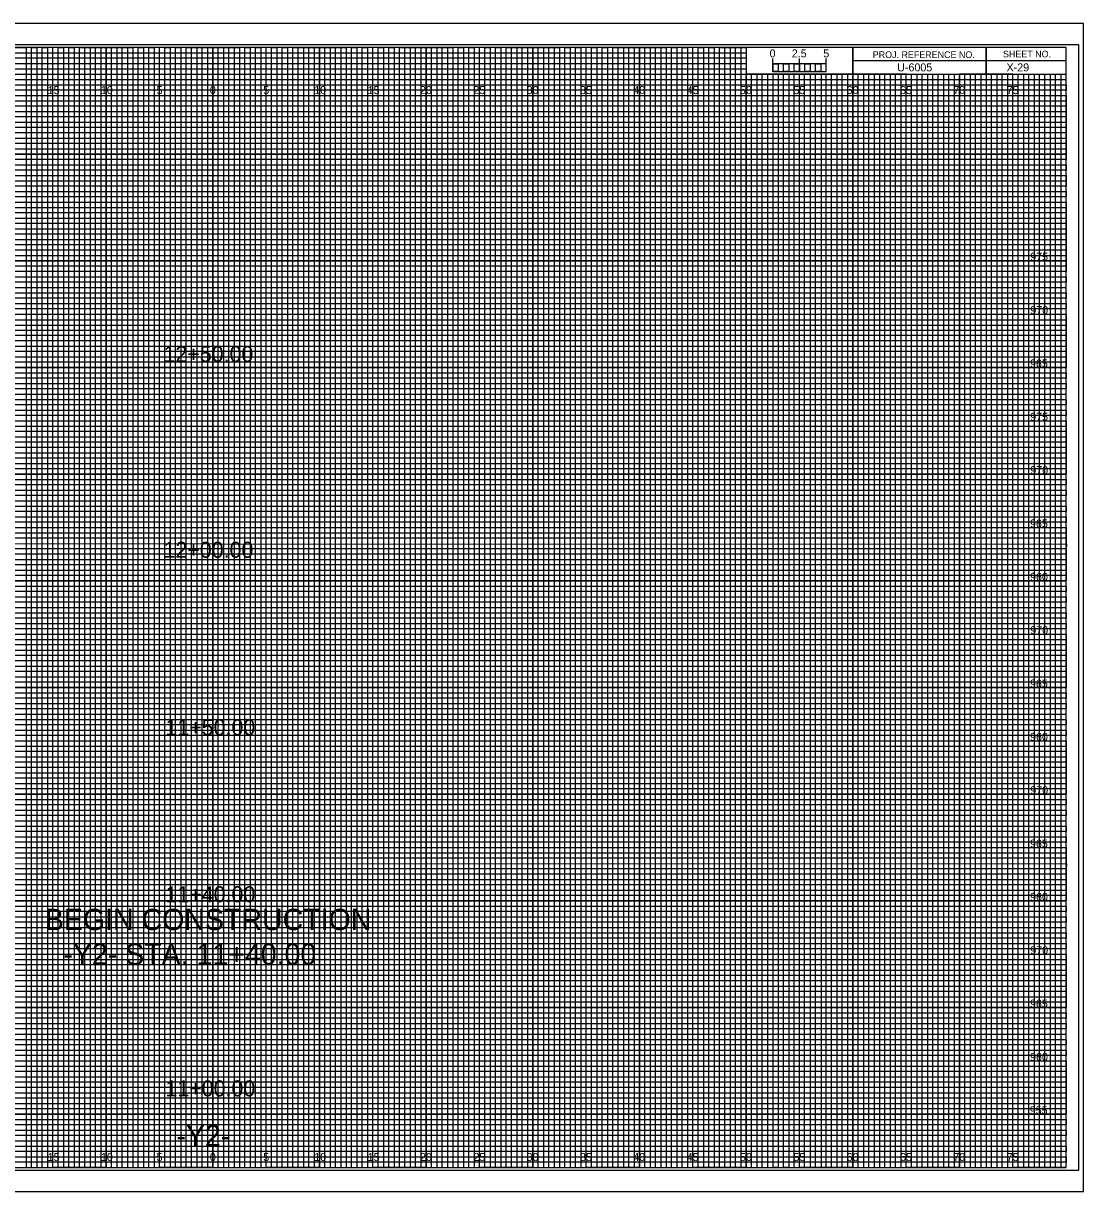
# Model space of a CAD drawing. Extents: x -7 to 162, y -2 to 107.
# Drawn here: x 62.2 to 161.7, y -2.3 to 107.3 of the extents above; entities that cross this region are included whole.
import ezdxf

# ---------------------------------------------------------------- set-up
doc = ezdxf.new("R2010")
doc.units = 0
for name, color, linetype in [('Prop XS Alignment Label', 7, 'Continuous'), ('Prop XS Bar Scale Labels', 7, 'Continuous'), ('Prop XS Elevation Labels', 7, 'Continuous'), ('Prop XS Label Text', 7, 'Continuous'), ('Prop XS Offset Labels', 7, 'Continuous'), ('Prop XS Project Number', 7, 'Continuous'), ('Prop XS Sheet Number', 7, 'Continuous'), ('Prop XS Station Labels', 7, 'Continuous'), ('Sheet Cross Section CELL', 7, 'Continuous'), ('Sheet Cross Section Grid Major CELL', 7, 'Continuous'), ('Sheet Cross Section Grid Middle CELL', 7, 'Continuous'), ('Sheet Cross Section Grid Minor 1 CELL', 7, 'Continuous'), ('Sheet Cross Section Grid Minor 2 CELL', 7, 'Continuous'), ('Sheet Cross Section Scale CELL', 7, 'Continuous'), ('Sheet Cutting Line CELL', 7, 'Continuous'), ('Sheet DOT Grid CELL', 7, 'Continuous'), ('Sheet Plot Border Inside CELL', 7, 'Continuous'), ('Sheet Plot Border Outside CELL', 7, 'Continuous')]:
    doc.layers.add(name, color=color, linetype=linetype)

msp = doc.modelspace()

# ---------------------------------------------------------------- linework, layer by layer
at = {"layer": 'Sheet Cross Section CELL'}
for p, q in [((152.5, 105), (152.5, 102.5)), ((152.5, 102.5), (152.5, 105)), ((160, 103.75), (140, 103.75)), ((140, 103.75), (140, 102.5)), ((140, 102.5), (160, 102.5))]:
    msp.add_line(p, q, dxfattribs=at)
for points in [[(160, 105), (0, 105), (0, 0), (160, 0)], [(140, 105), (130, 105), (130, 102.52), (140, 102.52)], [(160, 105), (140, 105), (140, 102.5), (160, 102.5)]]:
    msp.add_lwpolyline(points, close=True, dxfattribs=at)
at = {"layer": 'Sheet Cross Section Grid Major CELL'}
for p, q in [((65, 105), (60, 105)), ((65, 0), (65, 105)), ((75, 105), (70, 105)), ((70, 105), (70, 0)), ((75, 0), (75, 105)), ((85, 105), (80, 105)), ((80, 105), (80, 0)), ((85, 0), (85, 105)), ((95, 105), (90, 105)), ((90, 105), (90, 0)), ((95, 0), (95, 105)), ((105, 105), (100, 105)), ((100, 105), (100, 0)), ((105, 0), (105, 105)), ((115, 105), (110, 105)), ((110, 105), (110, 0)), ((115, 0), (115, 105)), ((125, 105), (120, 105)), ((120, 105), (120, 0)), ((125, 0), (125, 105)), ((130, 105), (130, 0)), ((135, 0), (135, 102.5)), ((145, 102.5), (140, 102.5)), ((140, 102.5), (140, 0)), ((145, 0), (145, 102.5)), ((155, 102.5), (150, 102.5)), ((150, 102.5), (150, 0)), ((155, 0), (155, 102.5)), ((70, 0), (65, 0)), ((80, 0), (75, 0)), ((90, 0), (85, 0)), ((100, 0), (95, 0)), ((110, 0), (105, 0)), ((120, 0), (115, 0)), ((130, 0), (125, 0)), ((140, 0), (135, 0)), ((150, 0), (145, 0)), ((160, 0), (155, 0)), ((160, 0), (160, 0))]:
    msp.add_line(p, q, dxfattribs=at)
for points in [[(0, 100), (160, 100), (160, 95), (0, 95)], [(0, 90), (160, 90), (160, 85), (0, 85)], [(0, 80), (160, 80), (160, 75), (0, 75)], [(0, 70), (160, 70), (160, 65), (0, 65)], [(0, 60), (160, 60), (160, 55), (0, 55)], [(0, 50), (160, 50), (160, 45), (0, 45)], [(0, 40), (160, 40), (160, 35), (0, 35)], [(0, 30), (160, 30), (160, 25), (0, 25)], [(0, 20), (160, 20), (160, 15), (0, 15)], [(0, 10), (160, 10), (160, 5), (0, 5)]]:
    msp.add_lwpolyline(points, dxfattribs=at)
at = {"layer": 'Sheet Cross Section Grid Middle CELL'}
for points in [[(57.5, 105), (62.5, 105), (62.5, 0), (67.5, 0), (67.5, 105), (72.5, 105), (72.5, 0), (77.5, 0), (77.5, 105), (82.5, 105), (82.5, 0), (87.5, 0), (87.5, 105), (92.5, 105), (92.5, 0), (97.5, 0), (97.5, 105), (102.5, 105), (102.5, 0), (107.5, 0), (107.5, 105), (112.5, 105), (112.5, 0), (117.5, 0), (117.5, 105), (122.5, 105), (122.5, 0), (127.5, 0), (127.5, 105), (129.97, 105), (130, 105), (130, 102.5), (132.5, 102.5), (132.5, 0), (137.5, 0), (137.5, 102.5), (142.5, 102.5), (142.5, 0), (147.5, 0), (147.5, 102.5), (152.5, 102.5), (152.5, 0), (157.5, 0), (157.5, 102.5)], [(0, 102.5), (137.5, 102.5)], [(0, 92.5), (160, 92.5), (160, 97.5), (0, 97.5)], [(0, 82.5), (160, 82.5), (160, 87.5), (0, 87.5)], [(0, 72.5), (160, 72.5), (160, 77.5), (0, 77.5)], [(0, 62.5), (160, 62.5), (160, 67.5), (0, 67.5)], [(0, 52.5), (160, 52.5), (160, 57.5), (0, 57.5)], [(0, 42.5), (160, 42.5), (160, 47.5), (0, 47.5)], [(0, 32.5), (160, 32.5), (160, 37.5), (0, 37.5)], [(0, 22.5), (160, 22.5), (160, 27.5), (0, 27.5)], [(0, 12.5), (160, 12.5), (160, 17.5), (0, 17.5)], [(0, 2.5), (160, 2.5), (160, 7.5), (0, 7.5)]]:
    msp.add_lwpolyline(points, dxfattribs=at)
at = {"layer": 'Sheet Cross Section Grid Minor 1 CELL'}
for p, q in [((0, 104.5), (130, 104.5)), ((130, 104.5), (130, 103.99)), ((130, 103.99), (0, 103.99)), ((0, 103.5), (130, 103.5)), ((130, 102.95), (0, 102.95)), ((130, 103.5), (130, 102.95)), ((0, 102), (160, 102))]:
    msp.add_line(p, q, dxfattribs=at)
for points in [[(0, 101.5), (135, 101.5), (160, 101.5), (160, 101), (0, 101)], [(0, 100.5), (160, 100.5), (160, 99.5), (0, 99.5)], [(0, 99), (160, 99), (160, 98.5), (0, 98.49)], [(0, 98), (160, 98), (160, 97), (0, 97)], [(0, 96.5), (160, 96.5), (160, 96), (0, 96)], [(0, 95.5), (160, 95.5), (160, 94.5), (0, 94.5)], [(0, 94), (160, 94), (160, 93.5), (0, 93.5)], [(0, 93), (160, 93), (160, 92), (0, 92)], [(0, 91.5), (160, 91.5), (160, 91), (0, 91)], [(0, 90.5), (160, 90.5), (160, 89.5), (0, 89.5)], [(0, 89), (160, 89), (160, 88.5), (0, 88.5)], [(0, 88), (160, 88), (160, 86.98), (160, 86.5), (160, 86), (0, 86)], [(0, 87), (160, 87), (160, 86.5), (0, 86.5)], [(0, 85.5), (160, 85.5), (160, 84.5), (0, 84.52)], [(0, 84.52), (160, 84.5), (160, 84), (0, 84)], [(0, 83.5), (160, 83.5), (160, 83), (0, 83)], [(0, 82), (160, 82), (160, 81.5), (0, 81.5)], [(0, 81), (160, 81), (160, 80.5), (0, 80.5)], [(-0.04, 79.45), (160, 79.45), (160, 78.94), (-0.04, 78.94)], [(0, 78.5), (160, 78.5), (160, 78), (0, 78)], [(0, 77), (160, 77), (160, 76.5), (0, 76.5)], [(0, 76), (160, 76), (160, 75.5), (0, 75.5)], [(0, 74.5), (160, 74.5), (160, 74), (0, 74)], [(0, 73.5), (160, 73.5), (160, 73), (0, 73)], [(0, 72), (160, 72), (160, 71.5), (0, 71.5)], [(0, 71), (160, 71), (160, 70.5), (0, 70.5)], [(0, 69.5), (160, 69.5), (160, 68.99), (0, 69)], [(0, 68.5), (160, 68.5), (160, 68), (0, 68)], [(0, 67), (160, 67), (160, 66.5), (0, 66.5)], [(0, 66), (160, 66), (160, 65.5), (0, 65.5)], [(0, 64.5), (160, 64.5), (160, 64), (0, 64)], [(0, 63.5), (160, 63.5), (160, 63), (0, 63)], [(0, 62), (160, 62), (160, 61.5), (0, 61.5)], [(0, 61), (160, 61), (160, 60.5), (0, 60.5)], [(0, 59.5), (160, 59.5), (160, 59), (0, 59)], [(0, 58.5), (160.03, 58.45), (160, 58), (0, 58)], [(0, 57), (160, 57), (160, 56.5), (0, 56.5)], [(0, 56), (160, 56), (160, 55.5), (0, 55.5)], [(0, 54.5), (160, 54.5), (160, 54), (0, 54)], [(0, 53.5), (160, 53.5), (160, 53), (0, 53)], [(0, 52), (160, 52), (160, 51.5), (0, 51.5)], [(0, 51), (160, 51), (160, 50.5), (0, 50.5)], [(0, 49.5), (160, 49.5), (160, 49), (0, 49)], [(0, 48.5), (160, 48.5), (160, 48), (0, 48)], [(0, 47), (160, 47), (160, 46.5), (0, 46.5)], [(0, 46), (160, 46), (160, 45.5), (0, 45.5)], [(0, 44.5), (160, 44.5), (160, 44), (0, 44)], [(0, 43.5), (160, 43.5), (160, 43), (0, 43)], [(0, 42), (160, 42), (160, 41.5), (0, 41.5)], [(0, 41), (160, 41), (160, 40.5), (0, 40.5)], [(0, 39.5), (160, 39.5), (160, 38.99), (0, 39)], [(0, 38.5), (160, 38.5), (160, 38), (0, 38)], [(0, 37), (160, 37), (160, 36.5), (0, 36.5)], [(0, 36), (160, 36), (160, 35.5), (0, 35.5)], [(0, 34.5), (160, 34.5), (160, 34), (0, 34)], [(0, 33.5), (160, 33.5), (160, 33), (0, 33)], [(0, 32), (160, 32), (160, 31.5), (0, 31.5)], [(0, 31), (160, 31), (160, 30.5), (0, 30.5)], [(0, 29.5), (160, 29.5), (160, 29), (0, 29)], [(0, 28.5), (160.03, 28.46), (160, 28), (0, 28)], [(0, 27), (160, 27), (160, 26.5), (0, 26.5)], [(0, 26), (160, 26), (160, 25.5), (0, 25.5)], [(0, 24.5), (160, 24.5), (160, 24), (0, 24)], [(0, 23.5), (160, 23.5), (160, 23), (0, 23)], [(0, 22), (160, 22), (160, 21.5), (0, 21.5)], [(0, 21), (160, 21), (160, 20.5), (0, 20.5)], [(0, 19.5), (160, 19.5), (160, 19), (0, 19)], [(0, 18.5), (160, 18.5), (160, 18), (0, 18)], [(0, 17), (160, 17), (160, 16.5), (0, 16.5)], [(0, 16), (160, 16), (160, 15.5), (0, 15.5)], [(0, 14.5), (160, 14.5), (160, 14), (0, 14)], [(0, 13.5), (160, 13.5), (160, 13), (0, 13)], [(0, 12), (160, 12), (160, 11.5), (0, 11.5)], [(0, 11), (160, 11), (160, 10.5), (0, 10.5)], [(0, 9.5), (160, 9.5), (160, 9), (0, 9)], [(0, 8.5), (160, 8.5), (160, 8), (0, 8)], [(0, 7), (160, 7), (160, 6.5), (0, 6.5)], [(0, 6), (160, 6), (160, 5.5), (0, 5.5)], [(0, 4.5), (160, 4.5), (160, 4), (0, 4)], [(0, 3.5), (160, 3.5), (160, 3), (0, 3)], [(0, 2), (160, 2), (160, 1.5), (0, 1.5)], [(0, 1), (160, 1), (160, 0.5), (0, 0.5)]]:
    msp.add_lwpolyline(points, dxfattribs=at)
at = {"layer": 'Sheet Cross Section Grid Minor 2 CELL'}
for p, q in [((133.5, 102.5), (133, 102.5)), ((133, 102.5), (133, 0)), ((133.5, 0), (133.5, 102.5)), ((134.5, 102.5), (134, 102.5)), ((134, 102.5), (134, 0)), ((134.5, 0), (134.5, 102.5)), ((133, 0), (132.5, 0)), ((134, 0), (133.5, 0))]:
    msp.add_line(p, q, dxfattribs=at)
for points in [[(62.5, 0), (63, 0), (63, 105), (63.5, 105), (63.5, 0)], [(63.5, 0), (64, 0), (64, 105), (64.5, 105), (64.5, 0)], [(65, 0), (65.5, 0), (65.5, 105), (66, 105), (66, 0)], [(66, 0), (66.5, 0), (66.5, 105), (67, 105), (67, 0)], [(67.5, 0), (68, 0), (68, 105), (68.5, 105), (68.5, 0)], [(68.5, 0), (69, 0), (69, 105), (69.5, 105), (69.5, 0)], [(70, 0), (70.5, 0), (70.5, 105), (71, 105), (71, 0)], [(71, 0), (71.5, 0), (71.5, 105), (72, 105), (72, 0)], [(72.5, 0), (73, 0), (73, 105), (73.5, 105), (73.5, 0)], [(73.5, 0), (74, 0), (74, 105), (74.5, 105), (74.5, 0)], [(75, 0), (75.5, 0), (75.5, 105), (76, 105), (76, 0)], [(76, 0), (76.5, 0), (76.5, 105), (77, 105), (77, 0)], [(77.5, 0), (78, 0), (78, 105), (78.5, 105), (78.5, 0)], [(78.5, 0), (79, 0), (79, 105), (79.5, 105), (79.5, 0)], [(80, 0), (80.5, 0), (80.5, 105), (81, 105), (81, 0)], [(81, 0), (81.5, 0), (81.5, 105), (82, 105), (82, 0)], [(82.5, 0), (83, 0), (83, 105), (83.5, 105), (83.5, 0)], [(83.5, 0), (84, 0), (84, 105), (84.5, 105), (84.5, 0)], [(85, 0), (85.5, 0), (85.5, 105), (86, 105), (86, 0)], [(86, 0), (86.5, 0), (86.5, 105), (87, 105), (87, 0)], [(87.5, 0), (88, 0), (88, 105), (88.5, 105), (88.5, 0)], [(88.5, 0), (89, 0), (89, 105), (89.5, 105), (89.5, 0)], [(90, 0), (90.5, 0), (90.5, 105), (91, 105), (91, 0)], [(91, 0), (91.5, 0), (91.5, 105), (92, 105), (92, 0)], [(92.5, 0), (93, 0), (93, 105), (93.5, 105), (93.5, 0)], [(93.5, 0), (94, 0), (94, 105), (94.5, 105), (94.5, 0)], [(95, 0), (95.5, 0), (95.5, 105), (96, 105), (96, 0)], [(96, 0), (96.5, 0), (96.5, 105), (97, 105), (97, 0)], [(97.5, 0), (98, 0), (98, 105), (98.5, 105), (98.5, 0)], [(98.5, 0), (99, 0), (99, 105), (99.5, 105), (99.5, 0)], [(100, 0), (100.5, 0), (100.5, 105), (101, 105), (101, 0)], [(101, 0), (101.5, 0), (101.5, 105), (102, 105), (102, 0)], [(102.5, 0), (103, 0), (103, 105), (103.5, 105), (103.5, 0)], [(103.5, 0), (104, 0), (104, 105), (104.5, 105), (104.5, 0)], [(105, 0), (105.5, 0), (105.5, 105), (106, 105), (106, 0)], [(106, 0), (106.5, 0), (106.5, 105), (107, 105), (107, 0)], [(107.5, 0), (108, 0), (108, 105), (108.5, 105), (108.5, 0)], [(108.5, 0), (109, 0), (109, 105), (109.5, 105), (109.5, 0)], [(110, 0), (110.5, 0), (110.5, 105), (111, 105), (111, 0)], [(111, 0), (111.5, 0), (111.5, 105), (112, 105), (112, 0)], [(112.5, 0), (113, 0), (113, 105), (113.5, 105), (113.5, 0)], [(113.5, 0), (114, 0), (114, 105), (114.5, 105), (114.5, 0)], [(115, 0), (115.5, 0), (115.5, 105), (116, 105), (116, 0)], [(116, 0), (116.5, 0), (116.5, 105), (117, 105), (117, 0)], [(117.5, 0), (118, 0), (118, 105), (118.5, 105), (118.5, 0)], [(118.5, 0), (119, 0), (119, 105), (119.5, 105), (119.5, 0)], [(120, 0), (120.5, 0), (120.5, 105), (121, 105), (121, 0)], [(121, 0), (121.5, 0), (121.5, 105), (122, 105), (122, 0)], [(122.5, 0), (123, 0), (123, 105), (123.5, 105), (123.5, 0)], [(123.5, 0), (124, 0), (124, 105), (124.5, 105), (124.5, 0)], [(125, 0), (125.5, 0), (125.5, 105), (126, 105), (126, 0)], [(126, 0), (126.5, 0), (126.5, 105), (127, 105), (127, 0)], [(127.5, 0), (128, 0), (128, 105), (128.5, 105), (128.5, 0)], [(128.5, 0), (129, 0), (129, 105), (129.5, 105), (129.5, 0)], [(130, 0), (130.5, 0), (130.5, 102.5), (131.01, 102.5), (131.01, 0)], [(131, 0), (131.5, 0), (131.5, 102.5), (132, 102.5), (132, 0)], [(135, 0), (135.49, 0), (135.49, 102.5), (136, 102.5), (136, 0)], [(136, 0), (136.5, 0), (136.5, 102.5), (137.03, 102.5), (137.03, 0)], [(137.5, 0), (138, 0), (138, 102.5), (138.5, 102.5), (138.5, 0)], [(138.5, 0), (139, 0), (139, 102.5), (139.5, 102.5), (139.5, 0)], [(140, 0), (140.5, 0), (140.5, 102.5), (141, 102.5), (141, 0)], [(141, 0), (141.5, 0), (141.5, 102.5), (142, 102.5), (142, 0)], [(142.5, 0), (143, 0), (143, 102.5), (143.5, 102.5), (143.5, 0)], [(143.5, 0), (144, 0), (144, 102.5), (144.5, 102.5), (144.5, 0)], [(145, 0), (145.5, 0), (145.5, 102.5), (146, 102.5), (146, 0)], [(146, 0), (146.5, 0), (146.5, 102.5), (147, 102.5), (147, 0)], [(147.5, 0), (148, 0), (148, 102.5), (148.5, 102.5), (148.5, 0)], [(148.5, 0), (149, 0), (149, 102.5), (149.5, 102.5), (149.5, 0)], [(150, 0), (150.5, 0), (150.5, 102.5), (151, 102.5), (151, 0)], [(151, 0), (151.5, 0), (151.5, 102.5), (152, 102.5), (152, 0)], [(152.5, 0), (153, 0), (153, 102.5), (153.5, 102.5), (153.5, 0)], [(153.5, 0), (154, 0), (154, 102.5), (154.5, 102.5), (154.5, 0)], [(155, 0), (155.5, 0), (155.5, 102.5), (156, 102.5), (156, 0)], [(156, 0), (156.5, 0), (156.5, 102.5), (157, 102.5), (157, 0)], [(157.5, 0), (158, 0), (158, 102.5), (158.5, 102.5), (158.5, 0)], [(158.5, 0), (159, 0), (159, 102.5), (159.5, 102.5), (159.5, 0)]]:
    msp.add_lwpolyline(points, dxfattribs=at)
at = {"layer": 'Sheet Cross Section Scale CELL'}
for p, q in [((132.5, 102.75), (132.5, 103.95)), ((132.5, 103.45), (132.5, 103.95)), ((135, 102.75), (135, 103.95)), ((137.5, 102.75), (137.5, 103.95)), ((137.5, 103.45), (137.5, 103.95))]:
    msp.add_line(p, q, dxfattribs=at)
for points in [[(137.5, 103.45), (132.5, 103.45), (132.5, 102.75), (137.5, 102.75)], [(132.5, 103.45), (133, 103.45), (133, 102.75), (132.5, 102.75)], [(133.5, 103.45), (134, 103.45), (134, 102.75), (133.5, 102.75)], [(134.5, 103.45), (135, 103.45), (135, 102.75), (134.5, 102.75)], [(135.5, 103.45), (136, 103.45), (136, 102.75), (135.5, 102.75)], [(136.5, 103.45), (137, 103.45), (137, 102.75), (136.5, 102.75)]]:
    msp.add_lwpolyline(points, close=True, dxfattribs=at)
at = {"layer": 'Sheet Cutting Line CELL'}
for p, q in [((161.65, 107.25), (-6.7, 107.25)), ((-6.7, -2.25), (161.65, -2.25))]:
    msp.add_line(p, q, dxfattribs=at)
at = {"layer": 'Sheet DOT Grid CELL'}
for p, q in [((65, 0), (65, 105)), ((70, 0), (70, 105)), ((75, 0), (75, 105)), ((80, 0), (80, 105)), ((85, 0), (85, 105)), ((90, 0), (90, 105)), ((95, 0), (95, 105)), ((100, 0), (100, 105)), ((105, 0), (105, 105)), ((110, 0), (110, 105)), ((115, 0), (115, 105)), ((120, 0), (120, 105)), ((125, 0), (125, 105)), ((130, 0), (130, 102.34)), ((135, 0), (135, 102.34)), ((140, 0), (140, 102.34)), ((145, 0), (145, 102.34)), ((150, 0), (150, 102.34)), ((155, 0), (155, 102.34)), ((0, 100), (160, 100)), ((0, 95), (160, 95)), ((0, 90), (160, 90)), ((0, 85), (160, 85)), ((0, 80), (160, 80)), ((0, 75), (160, 75)), ((0, 70), (160, 70)), ((0, 65), (160, 65)), ((0, 60), (160, 60)), ((0, 55), (160, 55)), ((0, 50), (160, 50)), ((0, 45), (160, 45)), ((0, 40), (160, 40)), ((0, 35), (160, 35)), ((0, 30), (160, 30)), ((0, 25), (160, 25)), ((0, 20), (160, 20)), ((0, 15), (160, 15)), ((0, 10), (160, 10)), ((0, 5), (160, 5))]:
    msp.add_line(p, q, dxfattribs=at)
at = {"layer": 'Sheet Plot Border Inside CELL'}
msp.add_lwpolyline([(-5.4, -0.25), (161.2, -0.25), (161.2, 105.25), (-5.4, 105.25)], close=True, dxfattribs=at)
at = {"layer": 'Sheet Plot Border Outside CELL'}
msp.add_lwpolyline([(-6.7, -2.25), (161.65, -2.25), (161.65, 107.25), (-6.7, 107.25)], close=True, dxfattribs=at)

# ---------------------------------------------------------------- texts
at = {"layer": 'Prop XS Alignment Label'}
msp.add_text('-Y2-', height=2, dxfattribs=at).set_placement((76.6, 2))
at = {"layer": 'Prop XS Bar Scale Labels'}
for s, p in [('2.5', (134.29, 104.06)), ('5', (137.24, 104.06))]:
    msp.add_text(s, height=0.75, dxfattribs=at).set_placement(p)
at = {"layer": 'Prop XS Elevation Labels'}
for s, p in [('975', (156.64, 85)), ('970', (156.65, 80)), ('965', (156.62, 75)), ('975', (156.64, 70)), ('970', (156.65, 65)), ('965', (156.62, 60)), ('960', (156.63, 55)), ('970', (156.65, 50)), ('965', (156.62, 45)), ('960', (156.63, 40)), ('970', (156.65, 35)), ('965', (156.62, 30)), ('960', (156.63, 25)), ('970', (156.65, 20)), ('965', (156.62, 15)), ('960', (156.63, 10)), ('955', (156.6, 5))]:
    msp.add_text(s, height=0.75, dxfattribs=at).set_placement(p)
at = {"layer": 'Prop XS Label Text'}
for s, p in [('BEGIN CONSTRUCTION', (64.27, 22.26)), ('-Y2- STA. 11+40.00', (66, 19.01))]:
    msp.add_text(s, height=2, dxfattribs=at).set_placement(p)
at = {"layer": 'Prop XS Offset Labels'}
for s, p in [('15', (64.53, 100.62)), ('10', (69.52, 100.62)), ('5', (74.74, 100.62)), ('0', (79.73, 100.62)), ('0', (79.73, 100.62)), ('5', (84.74, 100.62)), ('10', (89.52, 100.62)), ('15', (94.53, 100.62)), ('20', (99.43, 100.62)), ('25', (104.44, 100.62)), ('30', (109.43, 100.62)), ('35', (114.44, 100.62)), ('40', (119.43, 100.62)), ('45', (124.44, 100.62)), ('50', (129.43, 100.62)), ('55', (134.44, 100.62)), ('60', (139.43, 100.62)), ('65', (144.44, 100.62)), ('70', (149.43, 100.62)), ('75', (154.44, 100.62)), ('15', (64.53, 0.62)), ('10', (69.52, 0.62)), ('5', (74.74, 0.62)), ('0', (79.73, 0.62)), ('0', (79.73, 0.62)), ('5', (84.74, 0.62)), ('10', (89.52, 0.62)), ('15', (94.53, 0.62)), ('20', (99.43, 0.62)), ('25', (104.44, 0.62)), ('30', (109.43, 0.62)), ('35', (114.44, 0.62)), ('40', (119.43, 0.62)), ('45', (124.44, 0.62)), ('50', (129.43, 0.62)), ('55', (134.44, 0.62)), ('60', (139.43, 0.62)), ('65', (144.44, 0.62)), ('70', (149.43, 0.62)), ('75', (154.44, 0.62))]:
    msp.add_text(s, height=0.75, dxfattribs=at).set_placement(p)
at = {"layer": 'Prop XS Project Number'}
msp.add_text('U-6005', height=0.75, dxfattribs=at).set_placement((144.17, 102.75))
at = {"layer": 'Prop XS Sheet Number'}
msp.add_text('X-29', height=0.75, dxfattribs=at).set_placement((154.42, 102.75))
at = {"layer": 'Prop XS Station Labels'}
for s, p in [('12+50.00', (75.39, 75.51)), ('12+00.00', (75.39, 57.16)), ('11+50.00', (75.57, 40.52)), ('11+40.00', (75.57, 24.87)), ('11+00.00', (75.57, 6.68))]:
    msp.add_text(s, height=1.5, dxfattribs=at).set_placement(p)
at = {"layer": 'Sheet Cross Section CELL'}
for s, p in [('PROJ. REFERENCE NO.', (141.88, 104)), ('SHEET NO.', (154.09, 104.06))]:
    msp.add_text(s, height=0.625, dxfattribs=at).set_placement(p)
at = {"layer": 'Sheet Cross Section Scale CELL'}
msp.add_text('0', height=0.75, dxfattribs=at).set_placement((132.21, 104.06))

doc.saveas('drawing.dxf')
